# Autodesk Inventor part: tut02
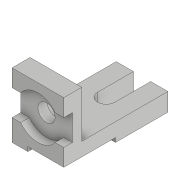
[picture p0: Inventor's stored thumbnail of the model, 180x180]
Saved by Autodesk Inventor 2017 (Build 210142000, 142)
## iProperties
Created: 2015-03
Part Number: tut02
Material: Generic
Document SubType Name: Modeling
Designer: Sandeep
Density: 1 g/cm^3
Appearance: Default
Author: Sandeep
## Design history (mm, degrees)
sketch "Sketch1"
  geometry: L1 (0, 90)-(25, 90); L2 (25, 90)-(25, 25); L3 (25, 25)-(145, 25); L4 (145, 25)-(145, 0); L5 (145, 0)-(0, 0); L6 (0, 0)-(0, 90)
  constraints: 12 end point, 5 perpendicular, 1 horizontal
  dimensions: "d0" = 25 distance of L1.start L1.end; "d1" = 90 distance of L5.end L1.start; "d2" = 145 distance of L4.end L5.end; "d3" = 25 distance of L3.end L4.end
extrude "Extrusion1" new body sketch "Sketch1" stored distance "d4" = 72; taper "d5" = 0 deg
sketch "Sketch2"
  geometry: L1 (0, 0)-(0, 145) reference; L2 (0, 0)-(-6, 0); L3 (-6, 0)-(-6, 72); L4 (-6, 72)-(0, 72); L5 (0, 72)-(0, 0)
  constraints: 8 end point, 2 parallel, 1 horizontal, 1 perpendicular
  dimensions: "d6" = 6 distance between parallel lines of L1 L3; "d7" = 72 distance of L2.end L3.end
extrude "Extrusion2" cut sketch "Sketch2" distance "d8" = 50; taper "d9" = 0 deg
sketch "Sketch3"
  geometry: L1 (12, -24)-(0, -24); L2 (0, -24)-(0, -60); L3 (0, -60)-(12, -60); L4 (36, -42)-(36, -101.863); L5 (60, -24)-(72, -24); L6 (72, -24)-(72, -60); L7 (72, -60)-(60, -60); L8 (72, 0)-(72, -84) reference; L9 (0, -90)-(0, 0) reference; L10 (72, -90)-(22, -90) reference; L11 (36, -42)-(119.122, -42); A1 r 30 centre (36, -42) between (12, -60) and (60, -60); A2 r 30 centre (36, -42) between (60, -24) and (12, -24); 1 further point
  constraints: 16 end point, 5 horizontal, 4 point on circle, 2 centre point, 2 collinear, 2 vertical, 1 perpendicular, 3 other
  dimensions: "d11" = 36 distance from line of L2 L4.start; "d12" = 48 distance from line of L10 L4.start; "d13" = 36 distance of L1.end L2.end; "d14" = 36 distance of L5.end L6.end; "d15" = 30 radius of A2
extrude "Extrusion3" cut sketch "Sketch3" distance "d16" = 12; taper "d17" = 0 deg
sketch "Sketch4"
  geometry: L1 (0, 120)-(72, 120) reference; L2 (24, 120)-(24, 70); L3 (48, 70)-(48, 120); L4 (0, 0)-(0, 120) reference; A1 r 12 centre (36, 70) between (24, 70) and (48, 70); 1 further point
  constraints: 4 end point, 2 point on circle, 2 point on line, 2 tangent, 1 centre point, 1 parallel, 1 vertical
  dimensions: "d18" = 36 distance from line of A1.centre L4; "d19" = 12 radius of A1; "d20" = 50 distance from line of L1 A1.centre
extrude "Extrusion4" cut sketch "Sketch4" stored distance "d21" = 12; taper "d22" = 0 deg
sketch "Sketch5"
  geometry: L1 (72, -24)-(72, -60) reference; C1 r 12 at (36, -42); 1 further point
  constraints: 1 centre point
  dimensions: "d23" = 24 diameter of C1; "d24" = 48 distance of point (36, -90) C1.centre; "d25" = 36 distance from line of L1 C1.centre
extrude "Extrusion5" cut sketch "Sketch5" stored distance "d26" = 12; taper "d27" = 0 deg
body "Solid1"
